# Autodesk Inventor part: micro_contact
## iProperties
Created: 2011-01
Part Number: micro_contact
Document SubType Name: Modeling
Designer: eric
Density: 1 g/cm^3
Mass: 1.27736 g
Surface Area: 12.191 cm^2
Volume: 1.27736 cm^3
Author: eric
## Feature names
1. Base1
